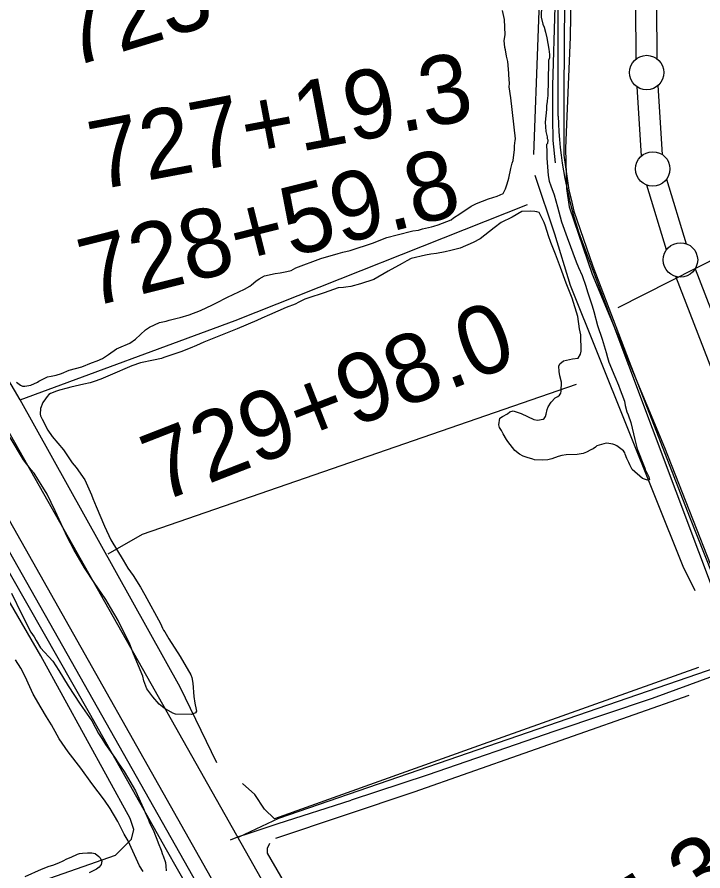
# Model space of a CAD drawing. Extents: x 3161564 to 3199464, y 849354 to 874788.
# Drawn here: x 3174720 to 3175717, y 856650 to 857891 of the extents above; entities that cross this region are included whole.
import ezdxf

# ---------------------------------------------------------------- set-up
doc = ezdxf.new("R2010")
doc.units = 0
for name, color, linetype in [('V-LEVE-TOET', 7, 'Continuous'), ('V-RAIL-TRAK', 7, 'Continuous'), ('V-ROAD-CNTR', 7, 'Continuous'), ('V-SITE-VEGE', 7, 'Continuous'), ('V-SURV-IDEN', 7, 'Continuous'), ('V-SURV-LINE', 7, 'Continuous'), ('V-TOPO-SHOR', 7, 'Continuous'), ('V-UTIL-LINE', 7, 'Continuous')]:
    doc.layers.add(name, color=color, linetype=linetype)

msp = doc.modelspace()

# ---------------------------------------------------------------- linework, layer by layer
at = {"layer": 'V-LEVE-TOET'}
for points in [[(3175459.5, 858433.4), (3175495.2, 858322.5), (3175506, 858284.9), (3175516.9, 858200.5), (3175516.8, 858052.2), (3175514.7, 857781.1), (3175514.5, 857690.4)], [(3175514.5, 857690.4), (3175521.9, 857639.7), (3175525.4, 857626.6), (3175529.3, 857609.1), (3175556.9, 857529.1), (3175609.8, 857390.7), (3175697.4, 857165), (3175774.1, 856970.3)]]:
    msp.add_lwpolyline(points, dxfattribs=at)
at = {"layer": 'V-RAIL-TRAK'}
msp.add_lwpolyline([(3175251.3, 856127.1), (3175191.8, 856229.7), (3175129.5, 856340.3), (3175033.4, 856512), (3174937.4, 856680.8), (3174825.3, 856879.4), (3174712.8, 857077.7), (3174579.2, 857317), (3174454.6, 857538.6), (3174360.6, 857704.4), (3174308.5, 857798.4), (3174259.3, 857884.6), (3174157.4, 858064.1)], dxfattribs=at)
at = {"layer": 'V-ROAD-CNTR'}
for points in [[(3173790.5, 858913.8), (3174494.5, 857665.3), (3175266.5, 856298.7), (3175883.3, 855209.3)], [(3175502.5, 857679.5), (3175499.2, 857712.1), (3175498.5, 857744.9), (3175498.6, 857792.1), (3175502, 857906.5), (3175503.1, 858136.9), (3175501.4, 858171.7), (3175498.1, 858227.8), (3175494.3, 858258), (3175490.5, 858283.2), (3175481.7, 858315.9), (3175383.7, 858580), (3175342.5, 858686.2), (3175337.8, 858698)], [(3173833.8, 858663.3), (3175153.4, 856327.2)], [(3175506.5, 858147.3), (3175506.2, 857747.4)], [(3175539.9, 857568.4), (3175847.7, 856748)], [(3175766.8, 856955.7), (3175100.3, 856726.3), (3175042.7, 856699.1)], [(3175766.3, 856945.6), (3175643.2, 856900.9), (3175501.7, 856853.1), (3175316.3, 856789.3), (3175205.8, 856753.1)], [(3175030.4, 856695.2), (3175040.9, 856699.6), (3175056, 856704.6), (3175099.5, 856718.8), (3175205.8, 856753.1)]]:
    msp.add_lwpolyline(points, dxfattribs=at)
msp.add_arc((3176110.3, 857768.3), 604.4, 181.9754, 199.3057, dxfattribs=at)
msp.add_spline([(3176879.1, 855651.9), (3176902.3, 855659.1), (3176934.1, 855667), (3176983.4, 855657.7), (3177040.7, 855639.1), (3177110.5, 855613.6), (3177170.6, 855601.8), (3177236.8, 855586.9), (3177274.8, 855573.5), (3177317.4, 855579.8), (3177362.6, 855595.7), (3177412, 855643.1), (3177451.7, 855679.2), (3177476.7, 855705.8), (3177478.3, 855737), (3177464.2, 855782.3), (3177430.8, 855833.4), (3177373, 855887.8), (3177287.8, 855954.8), (3177219.8, 855998.4), (3177153, 856039.4), (3177089.3, 856079.2), (3177023.4, 856134.3), (3176966.6, 856207.9), (3176895.2, 856290.1), (3176782.2, 856425.1), (3176693.2, 856545.3), (3176615.2, 856622.6), (3176543.9, 856726.5), (3176474.4, 856784.2), (3176414.4, 856823.6), (3176395.9, 856828), (3176350.8, 856806.2), (3176279.1, 856754.7), (3176211.6, 856707.4), (3176172.3, 856696.1), (3176141.1, 856702), (3176111.7, 856719.6), (3176032.6, 856777.4), (3175933.6, 856857.4), (3175839, 856930.3), (3175807.1, 856951.5), (3175770.1, 856958.7), (3175787.1, 856991.4), (3175795.1, 857040.7), (3175799.5, 857113.7), (3175810.8, 857206.9), (3175813.7, 857287.4), (3175807.8, 857386.8), (3175805.7, 857497.9), (3175801.9, 857543.6), (3175783.5, 857620.5), (3175760.2, 857716.1), (3175755.3, 857765.5), (3175754.5, 857815.6), (3175751.7, 857884.3), (3175756.3, 858015.5), (3175754.9, 858158.6), (3175753.1, 858270.8), (3175748.6, 858321.7), (3175736.5, 858372), (3175677.2, 858555.5), (3175602.2, 858747.1), (3175558.2, 858866.9), (3175502.5, 858986.2), (3175436.3, 859092.6), (3175371.2, 859185.1), (3175300.7, 859261.6), (3175219.1, 859367.2), (3175166.2, 859443.7), (3175175.3, 859507.1), (3175222, 859537.9), (3175285.3, 859568.3), (3175321.2, 859607.5), (3175310.3, 859667.2), (3175262.4, 859798.6), (3175224.6, 859877.9), (3175174.7, 859982), (3175144.8, 860115.4), (3175122.6, 860284.8), (3175088.4, 860568.6), (3175086.3, 860704.5), (3175072.2, 860854.5), (3175052.5, 860999.9), (3175047.5, 861166.8), (3175053.2, 861343.7), (3175066.7, 861550.4), (3175065.5, 861662.5), (3175040.2, 861767.8), (3175017.8, 861884.2), (3175008.4, 862033.9), (3174979.6, 862160.3), (3174952.1, 862274.6), (3174921.6, 862422.8), (3174897, 862525.5), (3174861.7, 862663.2), (3174841.1, 862738)], degree=3, dxfattribs=at)
at = {"layer": 'V-SITE-VEGE'}
for points in [[(3175482.5, 857908.4), (3175481.8, 857891.3), (3175484.2, 857881.3), (3175486, 857876.8), (3175488.1, 857869.3), (3175490.2, 857861.1), (3175492.9, 857844.8), (3175493.9, 857837), (3175493.8, 857832.2), (3175492.6, 857828.5), (3175492.2, 857824.4), (3175491.4, 857776.6), (3175491, 857774.3), (3175490.5, 857768.8), (3175489.7, 857762.5), (3175489.6, 857758.4), (3175489.4, 857756.9), (3175487.7, 857738.7), (3175488.5, 857725), (3175490.3, 857717.5), (3175490.6, 857714.9), (3175491.7, 857712.7), (3175490.8, 857707.5), (3175489.7, 857706.2), (3175489.8, 857695.1), (3175490.2, 857686.2), (3175491.8, 857661), (3175493.5, 857652.7), (3175496, 857646.2), (3175500.6, 857633.1), (3175505.6, 857615.6), (3175511.3, 857593.9), (3175519.4, 857570.8), (3175532.4, 857535.4), (3175536, 857527.1), (3175541.2, 857515.5), (3175546.9, 857500), (3175549, 857492.1), (3175555.7, 857471.8), (3175558.2, 857463.5), (3175563.6, 857442.9), (3175570.6, 857422.9), (3175576.3, 857403.6), (3175578.1, 857396.4), (3175580.2, 857389.5), (3175589, 857368.9), (3175594.3, 857356.2), (3175596.7, 857349.3), (3175599.2, 857343.1), (3175602.7, 857332.8), (3175603.8, 857326.6), (3175606.3, 857317.3), (3175608.4, 857313.2), (3175612.3, 857301.8), (3175617.7, 857277.4), (3175621.2, 857263.6), (3175632.5, 857235.7), (3175633.9, 857230.9), (3175635.3, 857228.9), (3175638.1, 857223), (3175638.8, 857220.6), (3175639.2, 857218.6), (3175636.4, 857218.2), (3175629.2, 857220.5), (3175613.9, 857233.5), (3175610.4, 857240.4), (3175609, 857243.8), (3175606.2, 857249.7), (3175603.7, 857255.9), (3175603.3, 857257.9), (3175601.3, 857260.7), (3175591.9, 857267.8), (3175588.8, 857269.5), (3175585.7, 857270.6), (3175580.1, 857271.5), (3175576, 857271.9), (3175562.9, 857268), (3175560.5, 857265.9), (3175557.4, 857263.8), (3175554, 857262), (3175547.8, 857258.9), (3175542.6, 857257.1), (3175534, 857255.3), (3175518.2, 857254.8), (3175512, 857254.1)], [(3174986.6, 857464.7), (3175004.1, 857472.8), (3175007.2, 857474.6), (3175013.7, 857477.7), (3175021.3, 857481.9), (3175026.1, 857484), (3175050.8, 857495.6), (3175058.4, 857500.2), (3175060.8, 857501.9), (3175067.3, 857507.5), (3175072.1, 857511), (3175080, 857515.2), (3175095.5, 857518.7), (3175102.4, 857519.5), (3175112.4, 857521.3), (3175118.6, 857523.1), (3175125.5, 857526.6), (3175161.6, 857540.3), (3175186.7, 857547.8), (3175193.6, 857549.6), (3175204.2, 857552.1), (3175238, 857563.4), (3175243.8, 857565.8), (3175257.6, 857570.8), (3175272.7, 857574.7), (3175295.1, 857580.4), (3175303.4, 857581.8), (3175309.2, 857583.6), (3175322.6, 857586.5), (3175325.7, 857587.5), (3175332.3, 857589.3), (3175351.2, 857596.7), (3175354.3, 857599.5), (3175363.5, 857605.1), (3175380, 857616.3), (3175387.9, 857620.5), (3175405.1, 857627.2), (3175417.8, 857631.1), (3175426.8, 857634.9), (3175429.8, 857641.5), (3175432.5, 857649.1), (3175434.9, 857657.1), (3175437.5, 857671.2), (3175439.5, 857678.8), (3175440.9, 857683), (3175442.8, 857698.9), (3175443.1, 857704.4), (3175444.1, 857712), (3175444.3, 857714.3), (3175437.5, 857774.1), (3175435.5, 857790.1), (3175436, 857794.9), (3175434.7, 857807.2), (3175434.8, 857810.1), (3175433.2, 857826.9), (3175432.5, 857830.6), (3175431.5, 857834.7), (3175429.8, 857844), (3175429.1, 857847), (3175428.1, 857857.4), (3175429.4, 857865.5), (3175428.3, 857888.1), (3175425.5, 857900.8)], [(3175512, 857254.1), (3175506.5, 857252.3), (3175497.5, 857249.1), (3175491.7, 857247.7), (3175483.7, 857247), (3175472, 857247.9), (3175469.6, 857248.6), (3175461.6, 857251.3), (3175455.7, 857252.9), (3175450.2, 857255.7), (3175443.3, 857261.1), (3175433.5, 857274.5), (3175431.4, 857277.2), (3175426.5, 857285.5), (3175424, 857290.3), (3175421.3, 857294.7), (3175420.2, 857298.5), (3175421.8, 857308.2), (3175425.6, 857310.6), (3175432.8, 857314.8), (3175436.2, 857317.3), (3175441.1, 857318.7), (3175452.8, 857315), (3175471.2, 857306.5), (3175476.4, 857305.2), (3175484.6, 857306.6), (3175486.3, 857307.7), (3175488, 857310.5), (3175489.1, 857313.9), (3175490.7, 857320.8), (3175492.1, 857324.6), (3175496.2, 857331.6), (3175502.3, 857337.8), (3175506.1, 857339.9), (3175508.5, 857341.7), (3175510.2, 857344.8), (3175510.9, 857347.6), (3175511.1, 857360.7), (3175509, 857370), (3175507.9, 857376.2), (3175507.5, 857383.8), (3175508.8, 857387.2), (3175514.3, 857391.4), (3175527.4, 857394.6), (3175535.7, 857395.4), (3175539.1, 857401.3), (3175540.1, 857405.8), (3175539.5, 857429.6), (3175537.7, 857438.2), (3175535.2, 857456.1), (3175526.7, 857482.9), (3175518.2, 857504.6), (3175510.1, 857527.3), (3175502.7, 857546.9), (3175496, 857563.7), (3175492.5, 857573.4), (3175488.2, 857587.5), (3175486.1, 857592.6), (3175478.7, 857607.4), (3175475.3, 857608.4), (3175472.5, 857608.7), (3175466.3, 857609), (3175453.9, 857608.9), (3175439.5, 857600.5), (3175423.7, 857592.5), (3175413.7, 857585.1), (3175393.2, 857569.1), (3175382.8, 857563.5), (3175363.9, 857555.4), (3175350.5, 857551.9), (3175342.3, 857550.1), (3175329.8, 857547.9), (3175321.6, 857546.8), (3175313.7, 857545.3), (3175292.7, 857540.4), (3175286.5, 857537.2), (3175279.9, 857533), (3175259.3, 857521.8), (3175238.7, 857509.9), (3175219.5, 857503.5), (3175205.4, 857499.6), (3175197.8, 857498.5), (3175194.7, 857498.2), (3175186.8, 857497.8), (3175166.5, 857490.7), (3175142.7, 857482.9), (3175138.6, 857481.1), (3175129.7, 857476.9), (3175124.5, 857474.1), (3175111.4, 857469.2), (3175087, 857458.3), (3175076, 857453.7), (3175068.8, 857450.2), (3175039.9, 857438.3), (3175001.1, 857422.8), (3174991.8, 857418.6), (3174981.1, 857414), (3174971.9, 857410.1), (3174958.4, 857404.8), (3174933.7, 857396.3), (3174930.2, 857394.9)], [(3174719.4, 857360.8), (3174725.3, 857356), (3174728.1, 857355), (3174731.5, 857354.7), (3174740.1, 857356.1), (3174749.8, 857360.7), (3174751.8, 857362.1), (3174764.5, 857368.4), (3174770, 857369.1), (3174777.3, 857370.6), (3174784.8, 857373.4), (3174796.2, 857378), (3174814.4, 857383), (3174828.5, 857388.6), (3174836.8, 857391.4), (3174844.3, 857394.9), (3174852.9, 857400.9), (3174864.9, 857409.2), (3174868, 857410.6), (3174884.2, 857417.3), (3174892.4, 857423.3), (3174906.8, 857436.5), (3174912.6, 857440.7), (3174927.1, 857447.3), (3174937, 857449.2), (3174941.2, 857450.6), (3174952.9, 857453.8), (3174957.4, 857454.8), (3174970.1, 857458.4), (3174986.6, 857464.7)], [(3174930.2, 857394.9), (3174918.5, 857392.4), (3174899.6, 857388.5), (3174887.2, 857384.2), (3174855.6, 857370.9), (3174842.2, 857364.9), (3174832.5, 857361.4), (3174826.3, 857359.6), (3174817.4, 857357.8), (3174798.5, 857353.2), (3174793.3, 857352.1), (3174781.9, 857348.9), (3174777.8, 857347.5), (3174768.9, 857344), (3174766.5, 857342.6), (3174764.1, 857339.8), (3174761.7, 857336.6), (3174757.6, 857330.8), (3174754.2, 857322.4), (3174753.9, 857314.2), (3174754.3, 857311.8), (3174756.7, 857306.6), (3174764.8, 857290.8), (3174771.4, 857281.5), (3174787.5, 857262), (3174800.4, 857243.1), (3174806, 857236.3), (3174818.5, 857218.8), (3174828.4, 857196.8), (3174830.5, 857191.3), (3174835.4, 857179.9), (3174847.4, 857151.4), (3174856.5, 857131.5), (3174874.3, 857101.6), (3174881.3, 857090.3), (3174889, 857079.3), (3174899.5, 857062.5), (3174906.1, 857051.2), (3174928.5, 857009.9), (3174931.7, 857002.7), (3174932.8, 857000), (3174934.8, 856997.6), (3174940.8, 856987.6), (3174957.2, 856961.9), (3174972.6, 856935.1), (3174974, 856931), (3174975.8, 856923), (3174977, 856903.7), (3174978.5, 856894.1), (3174980.6, 856884.8), (3174981, 856882.4), (3174979.6, 856880), (3174973.8, 856877.2), (3174950.7, 856877.7), (3174946.5, 856879.3), (3174934, 856886.8), (3174926.7, 856892.6), (3174917.3, 856903.3), (3174909, 856914.9), (3174904.7, 856926.6), (3174902.9, 856933.1), (3174889.6, 856965.5), (3174883.9, 856979.6), (3174867.1, 857014.3), (3174856.2, 857033.2), (3174849.3, 857044.5), (3174832.5, 857069.2), (3174818.2, 857090.8), (3174802.8, 857117.2), (3174793.7, 857134.8), (3174775.8, 857173.6), (3174763.8, 857197.6), (3174755.5, 857211.7), (3174750.6, 857219.6), (3174745, 857228.2), (3174740.8, 857233), (3174729.6, 857247.7), (3174710.4, 857280)], [(3174712.4, 857053.9), (3174727.1, 857022.8), (3174740.4, 856997), (3174745.1, 856990.3), (3174748, 856985), (3174754.5, 856974.2), (3174772.4, 856954.9), (3174781, 856941.4), (3174794.4, 856919), (3174811.8, 856892.3), (3174828.8, 856868.3), (3174838.5, 856850), (3174843.6, 856842.5), (3174849, 856833.9), (3174862, 856815.5), (3174867.1, 856807.2), (3174875.8, 856794.5), (3174880.8, 856786.2), (3174892.4, 856766.4), (3174904.2, 856740.6), (3174906.3, 856735), (3174911.3, 856724.2), (3174912.7, 856720), (3174917.8, 856709.6), (3174922.4, 856698.7), (3174923.5, 856696.1), (3174925.2, 856690.9), (3174929.5, 856680.1), (3174931.6, 856673.7), (3174932.7, 856671.9), (3174935.9, 856662.2), (3174936.5, 856657), (3174936.8, 856649.9)], [(3174778.7, 856847.3), (3174770.1, 856862.6), (3174763.2, 856874.2), (3174755.3, 856887), (3174743.7, 856906.8), (3174736.2, 856922.9), (3174732.7, 856931.9), (3174725.5, 856945), (3174717.9, 856957)], [(3174903.4, 856649), (3174898, 856657.6), (3174888.7, 856678.9), (3174881.9, 856693.5), (3174875.7, 856703.2), (3174866.8, 856721.9), (3174855.6, 856740.7), (3174847.3, 856753), (3174838.2, 856765.1), (3174828.8, 856777.1), (3174812.8, 856799.2), (3174794.6, 856822.9), (3174781.2, 856842), (3174778.7, 856847.3)], [(3174731.8, 856642.1), (3174755.9, 856652.5), (3174766.7, 856656.7), (3174772.1, 856658.5), (3174780.9, 856661.8), (3174787.3, 856664.6), (3174792.7, 856667.5), (3174799.1, 856669.8), (3174808, 856674.5), (3174810.9, 856675.5), (3174815.3, 856675.9), (3174822.7, 856676.2), (3174829, 856676.1), (3174833.9, 856675.1), (3174839.2, 856671.1), (3174841.1, 856669.1), (3174842.1, 856666.6), (3174843.5, 856664.2), (3174842.4, 856659.3), (3174839.4, 856655.5), (3174835.5, 856652.6), (3174825.1, 856647.4)]]:
    msp.add_lwpolyline(points, dxfattribs=at)
at = {"layer": 'V-SURV-LINE'}
for points in [[(3175619.9, 857830.7), (3175617.7, 858143.6)], [(3175647.7, 858143.8), (3175649.9, 857830.9)], [(3175627.7, 857689.7), (3175621.4, 857790)], [(3175651.3, 857791.8), (3175657.7, 857691.5)], [(3175664.1, 857655.9), (3175692.7, 857561.9)], [(3175664, 857553.2), (3175635.4, 857647.2)], [(3175705.4, 857525.2), (3175975, 856828.1)], [(3175947, 856817.2), (3175677.4, 857514.4)]]:
    msp.add_lwpolyline(points, dxfattribs=at)
for centre in [(3175635.1, 857810.8), (3175643.9, 857670.7), (3175684.2, 857538.4)]:
    msp.add_circle(centre, 25, dxfattribs=at)
at = {"layer": 'V-TOPO-SHOR'}
for points in [[(3175051.6, 859155.5), (3175181.2, 858983.2), (3175227.4, 858921), (3175259.4, 858857.1), (3175294.9, 858734.5), (3175364.2, 858560.4), (3175444.1, 858363.3), (3175472.6, 858267.3), (3175479.7, 858205.2), (3175483.2, 858031.1), (3175470.8, 857691.8)], [(3175328.7, 858796.7), (3175358.9, 858731), (3175390.8, 858654.6), (3175502.7, 858334.8), (3175511.6, 858304.6), (3175524.1, 858240.7), (3175527.6, 858109.2), (3175524.1, 857862.3), (3175517, 857700.7), (3175518.7, 857642.1), (3175522.3, 857615.4), (3175556, 857517.7), (3175660.8, 857265.5), (3175769.2, 856990.1)], [(3174724.7, 857334.8), (3174426.3, 857842.8), (3174412.1, 857864.1)], [(3173944.9, 857124.3), (3173861.4, 856715.7), (3173786.8, 856355.1), (3173831.2, 856339.1), (3173863.2, 856339.1), (3173905.8, 856351.5), (3173984, 856380), (3174065.7, 856394.2), (3174129.6, 856415.5), (3174275.3, 856467), (3174863.3, 856673.1), (3174886.3, 856696.1), (3174889.9, 856710.4), (3174884.6, 856726.3), (3174754.9, 856962.6), (3174529.3, 857351.6), (3174287.7, 857772.6)], [(3175472.6, 857661.6), (3175501, 857576.3), (3175524.1, 857501.7), (3175687.5, 857093.2), (3175705.3, 857057.6)], [(3175010.7, 856807.2), (3174957.4, 856917.3), (3174724.7, 857334.8), (3175037.3, 857450.2), (3175461.9, 857619)], [(3174563.5, 857416.9), (3175364.1, 855997.8), (3176042.8, 854791.6)], [(3174852.6, 857110.9), (3174902.3, 857139.4), (3175532.9, 857357.8)], [(3175710.6, 856945.7), (3175390.8, 856832), (3175094.2, 856725.5), (3175080, 856739.7), (3175065.8, 856761), (3175048, 856777)], [(3175696.4, 856904.9), (3175296.7, 856764.5), (3175096, 856697)], [(3175087.1, 856689.9), (3175083.5, 856682.8), (3175083.5, 856675.7), (3175245.2, 856396.8), (3175358.9, 856187.2), (3175602.2, 855757.3), (3175858, 855302.6), (3175925.5, 855183.6), (3176133.4, 854810.5), (3176147.6, 854789.2)]]:
    msp.add_lwpolyline(points, dxfattribs=at)
at = {"layer": 'V-UTIL-LINE'}
msp.add_line((3175593.9, 857469.1), (3175842.2, 857595.7), dxfattribs=at)

# ---------------------------------------------------------------- texts
at = {"layer": 'V-SURV-IDEN'}
for s, rotation, p in [('723+66.4', 17.0279, (3174797.5, 857817.5)), ('727+19.3', 10.7244, (3174835.7, 857639.5)), ('728+59.8', 14.1317, (3174825.6, 857469)), ('729+98.0', 21.3106, (3174927.9, 857185)), ('737+85.3', 31.6583, (3175293.2, 856331.9))]:
    msp.add_text(s, height=100, rotation=rotation, dxfattribs=at).set_placement(p)

doc.saveas('drawing.dxf')
